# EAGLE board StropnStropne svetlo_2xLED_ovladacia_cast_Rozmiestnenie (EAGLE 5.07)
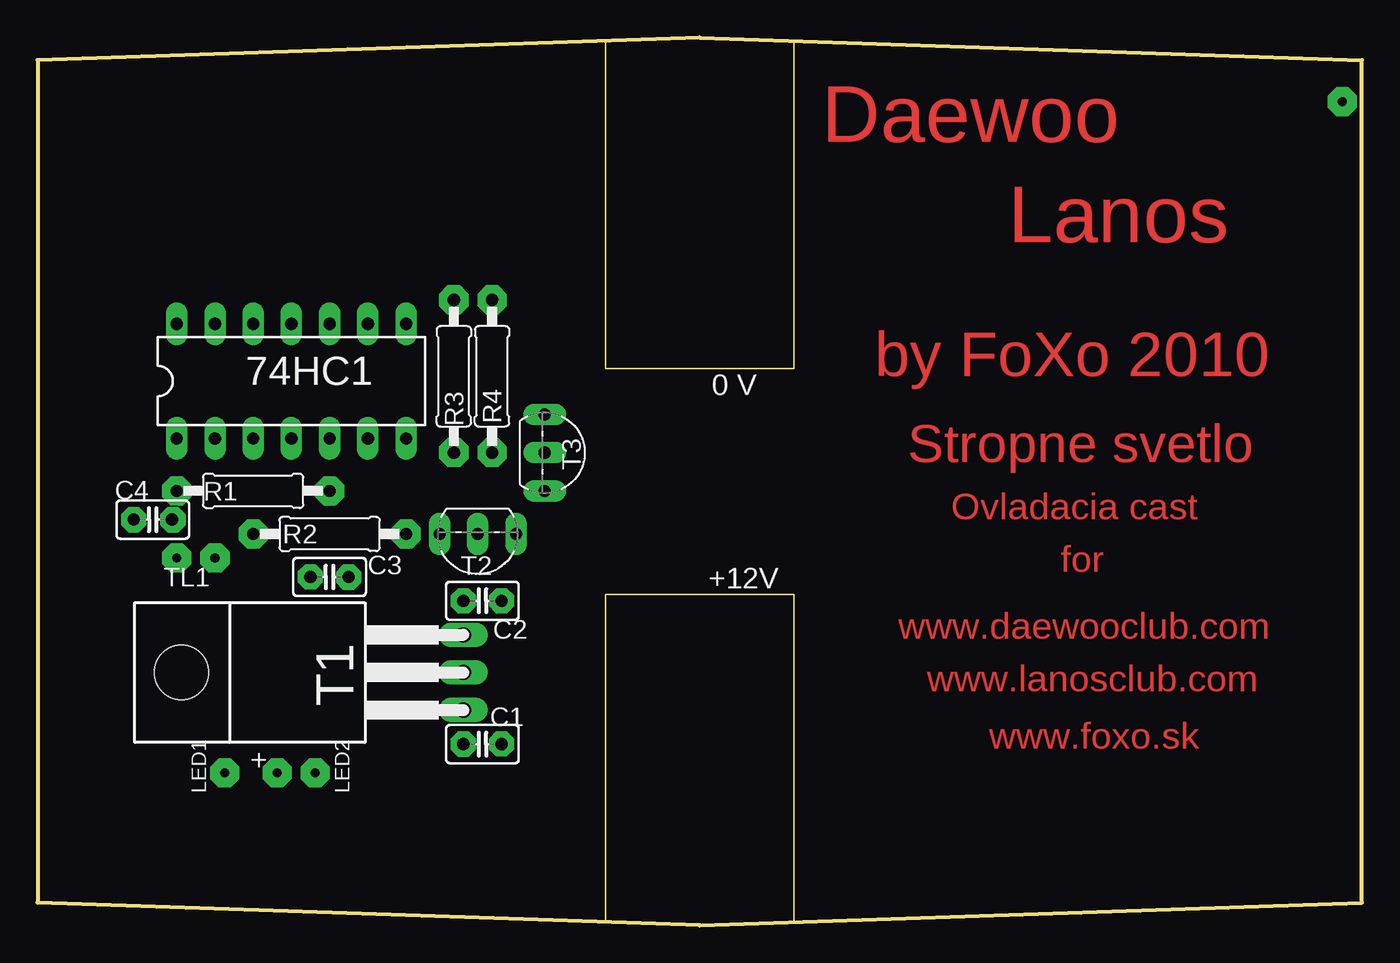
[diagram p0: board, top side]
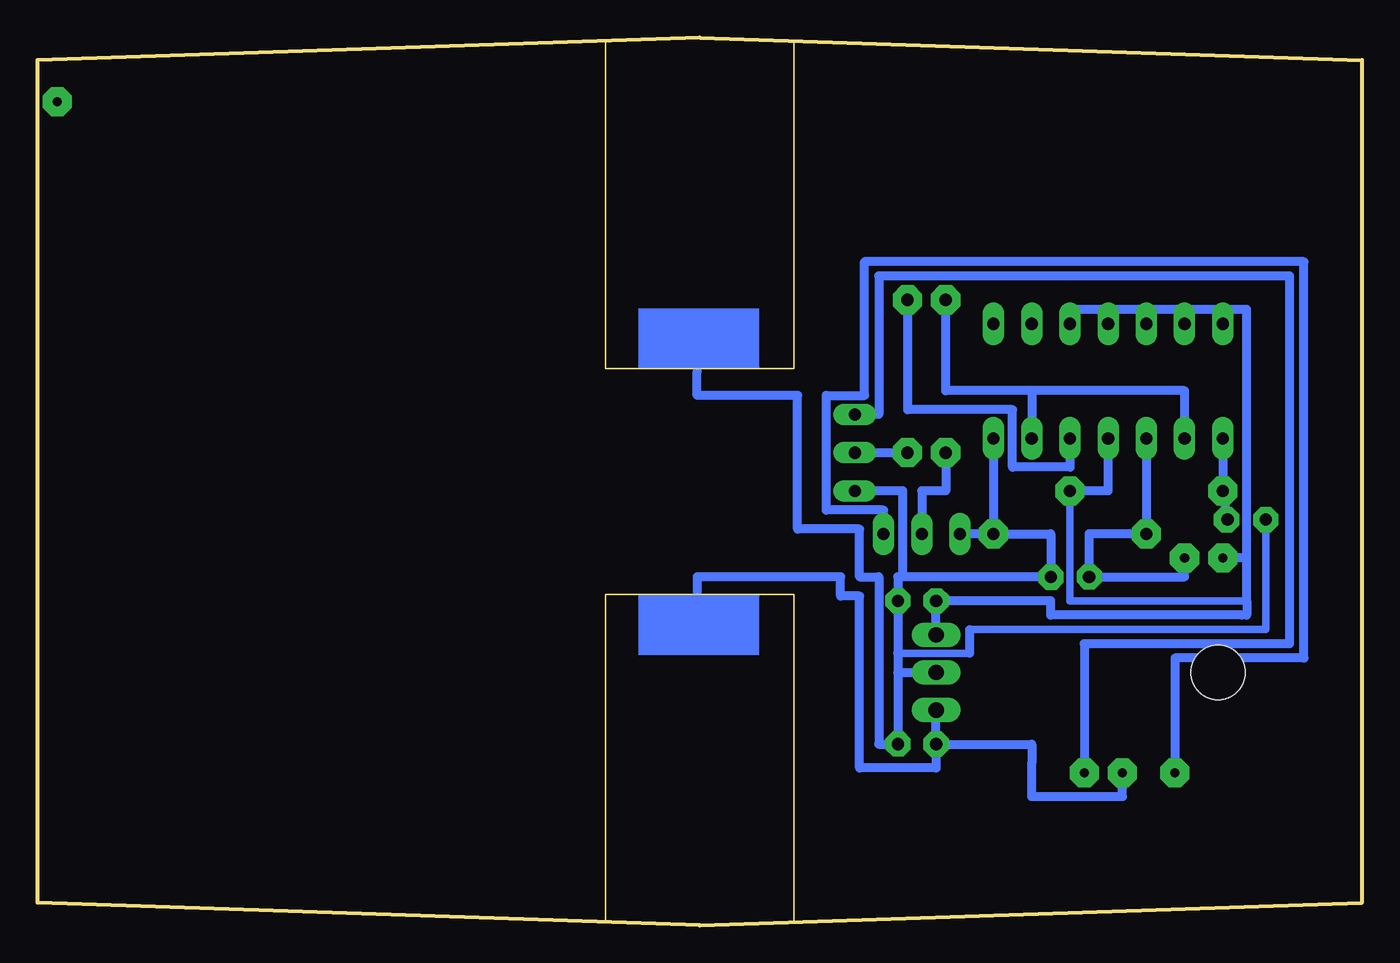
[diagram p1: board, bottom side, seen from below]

Size 88 x 59 mm. Coordinates in mm from the lower left corner, seen from the top.
Outline: 50.27,58.75 50.27,37 37.73,37 37.73,58.75
Outline: 50.27,0.25 50.27,22 37.73,22 37.73,0.25
Outline: 0,57.5 0,1.5 44,0 88,1.5 88,57.5 44,59 0,57.5
Copper layers (1*16): Top 0.035mm / dielectric 1.5mm / Bottom 0.035mm
Design rules "default *": minimum track width 10mil, minimum drill 24mil, track to track 8mil, track to pad 8mil, pad to pad 8mil, via to via 8mil, smd to smd 8mil, copper to edge 40mil, drill to drill 8mil, minimum pad ring 12mil, minimum via ring 8mil, stop-mask expansion 4mil, vias tented up to drill 0mil, thermal gap 10mil

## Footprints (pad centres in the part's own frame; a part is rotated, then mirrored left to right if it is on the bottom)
DIL14 = drill 0.813 long: 1 -7.62,-3.81; 2 -5.08,-3.81; 3 -2.54,-3.81; 4 0,-3.81; 5 2.54,-3.81; 6 5.08,-3.81; 7 7.62,-3.81; 8 7.62,3.81; 9 5.08,3.81; 10 2.54,3.81; 11 0,3.81; 12 -2.54,3.81; 13 -5.08,3.81; 14 -7.62,3.81
C025-025X050 = drill 0.813 octagon: 1 -1.27,0; 2 1.27,0
R-10 = drill 0.813 pad 1.93 octagon: 1 -5.08,0; 2 5.08,0
T-30 = drill 1.016 long: 1 -2.5,-18.735; 2 0,-18.735; 3 2.5,-18.735 | hole 3.6: 0,0
TO92-CBE = drill 0.813 long: B 0,0; C -2.54,0; E 2.54,0

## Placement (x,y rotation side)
74HC1  [DIL14]  16.86,36.17 0 top
C1  [C025-025X050]  29.56,12.04 0 top
C2  [C025-025X050]  29.56,21.57 0 top
C3  [C025-025X050]  19.4,23.16 180 top
C4  [C025-025X050]  7.66,26.96 180 top
R1  [R-10]  14.32,28.87 180 top
R2  [R-10]  19.4,26.01 0 top
R3  [R-10]  27.66,36.49 270 top
R4  [R-10]  30.2,36.49 270 top
T1  [T-30]  9.56,16.81 90 top
T2  [TO92-CBE]  29.25,26.01 180 top
T3  [TO92-CBE]  33.69,31.41 270 top

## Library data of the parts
74HC1 = 74ac-logic
C1-C4 = rcl
R1-R4 = #PaJa_21
T1-T3 = transistor

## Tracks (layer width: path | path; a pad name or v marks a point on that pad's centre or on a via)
S$1
  Bottom 0.61: 28.29,11.41 28.29,10.46 33.37,10.46 33.37,21.88 34.64,21.88 34.64,23.15 44.17,23.15 44.17,22.2
S$2
  Bottom 0.61: 32.74,28.87 30.52,28.87 30.52,23.15 | 30.83,22.2 30.83,23.15 30.52,23.15 | 21.31,23.15 30.52,23.15
S$5  (via drill 0.6 pad 1.68)
  other vias: 30.19,41.58
S$6  (via drill 0.6 pad 1.68)
  other vias: 8.99,26.95
S$7  (via drill 0.6 pad 1.68)
  other vias: 14.32,26.02
S$8  (via drill 0.6 pad 1.68)
  other vias: 20.66,23.14
S$9  (via drill 0.6 pad 1.68)
  other vias: 19.41,28.88
S$11  (via drill 0.6 pad 1.68)
  other vias: 9.23,28.88
S$12  (via drill 0.6 pad 1.68)
  other vias: 6.38,26.95
S$13  (via drill 0.6 pad 1.68)
  other vias: 30.83,21.56
S$14  (via drill 0.6 pad 1.68)
  other vias: 24.46,26.01
S$15  (via drill 0.6 pad 1.68)
  other vias: 30.83,12.05
S$17  (via drill 0.6 pad 1.68)
  other vias: 28.3,21.56
S$18  (via drill 0.6 pad 1.68)
  other vias: 28.3,12.04
S$19  (via drill 0.6 pad 1.68)
  other vias: 27.64,31.39
S$20  (via drill 0.6 pad 1.68)
  other vias: 30.2,31.4
S$21  (via drill 0.6 pad 1.68)
  other vias: 27.66,41.58
S$22  (via drill 0.6 pad 1.68)
  other vias: 18.12,23.16
S$47  (via drill 0.6 pad 1.93)
  other vias: 86.69,54.74
S$55  (via drill 0.6 pad 1.93)
  other vias: 9.24,24.43
S$56  (via drill 0.6 pad 1.93)
  other vias: 18.45,10.14
S$57  (via drill 0.6 pad 1.93)
  other vias: 12.42,10.14
S$60  (via drill 0.6 pad 1.93)
  other vias: 11.78,24.43
S$61  (via drill 0.6 pad 1.93)
  other vias: 15.91,10.14
S$62
  Bottom 0.61: 9.24,31.09 9.24,29.51
S$63
  Bottom 0.61: 18.77,28.87 16.86,28.87 16.86,31.09
S$64
  Bottom 0.61: 14.32,31.09 14.32,26.65
S$65
  Bottom 0.61: 24.48,31.09 24.48,26.65
S$66
  Bottom 0.61: 23.85,26.01 20.67,26.01 20.67,23.79
S$67
  Bottom 0.61: 14.96,26.01 18.13,26.01 18.13,23.79
S$68
  Bottom 0.61: 17.5,23.15 11.78,23.15 11.78,23.47
S$69
  Bottom 0.61: 28.29,12.68 28.29,13.63
S$70
  Bottom 0.5: 19.4,28.24 19.4,21.57 7.66,21.57
  Bottom 0.61: 19.4,40.93 7.66,40.93 7.66,24.42 | 7.66,24.42 8.61,24.42 | 7.66,20.62 7.66,21.57 7.66,24.42
S$71
  Bottom 0.61: 9.24,28.24 9.02,27.63
S$72
  Bottom 0.5: 26.07,18.08 30.83,18.08 | 26.07,19.66 6.38,19.66 6.38,26.33
  Bottom 0.61: 30.83,16.81 30.83,12.68 | 30.83,16.81 29.56,16.81 | 30.83,16.81 30.83,18.08 30.83,20.93 | 26.07,19.66 26.07,18.08
S$73
  Bottom 0.61: 28.29,19.98 28.29,20.93
S$74
  Bottom 0.61: 7.97,20.62 20.67,20.62 20.67,21.57 27.66,21.57
S$76
  Bottom 0.61: 27.66,12.04 21.94,12.04 21.94,10.77
S$77
  Bottom 0.61: 21.94,10.77 21.94,8.55 15.91,8.55 15.91,9.19
S$78
  Bottom 0.61: 27.66,40.93 27.66,35.54 21.94,35.54 | 11.78,33.63 11.78,35.54 21.94,35.54 | 21.94,35.54 21.94,33.63
S$79
  Bottom 0.61: 30.2,40.93 30.2,34.27 23.21,34.27 23.21,30.46 19.4,30.46 19.4,31.09
S$80
  Bottom 0.61: 25.12,26.01 26.07,26.01
S$81
  Bottom 0.61: 27.66,30.78 27.66,28.87 29.25,28.87 29.25,26.96
S$82
  Bottom 0.61: 32.74,31.41 30.83,31.41
S$83
  Bottom 0.61: 44.17,36.81 44.17,35.22 37.5,35.22 37.5,26.33 33.37,26.33 33.37,23.15 32.1,23.15 32.1,12.04 31.47,12.04
S$84
  Bottom 0.61: 18.45,10.77 18.45,18.71 4.8,18.71 4.8,43.16 32.1,43.16 32.1,33.95 32.74,33.95
S$85
  Bottom 0.61: 31.79,27.28 31.79,27.6 35.59,27.6 35.59,35.22 33.05,35.22 33.05,44.11 3.84,44.11 3.84,17.76 12.42,17.76 12.42,10.77
(copper drawn outside any net)
  shapes: Bottom area x2

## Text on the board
Top: Daewoo | Lanos | by FoXo 2010 | Stropne svetlo | Ovladacia cast | for | www.daewooclub.com | www.lanosclub.com | www.foxo.sk
tNames: 0 V | +12V | TL1 | LED1 | + | LED2
Doplnky: E | B | C | E | B | C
